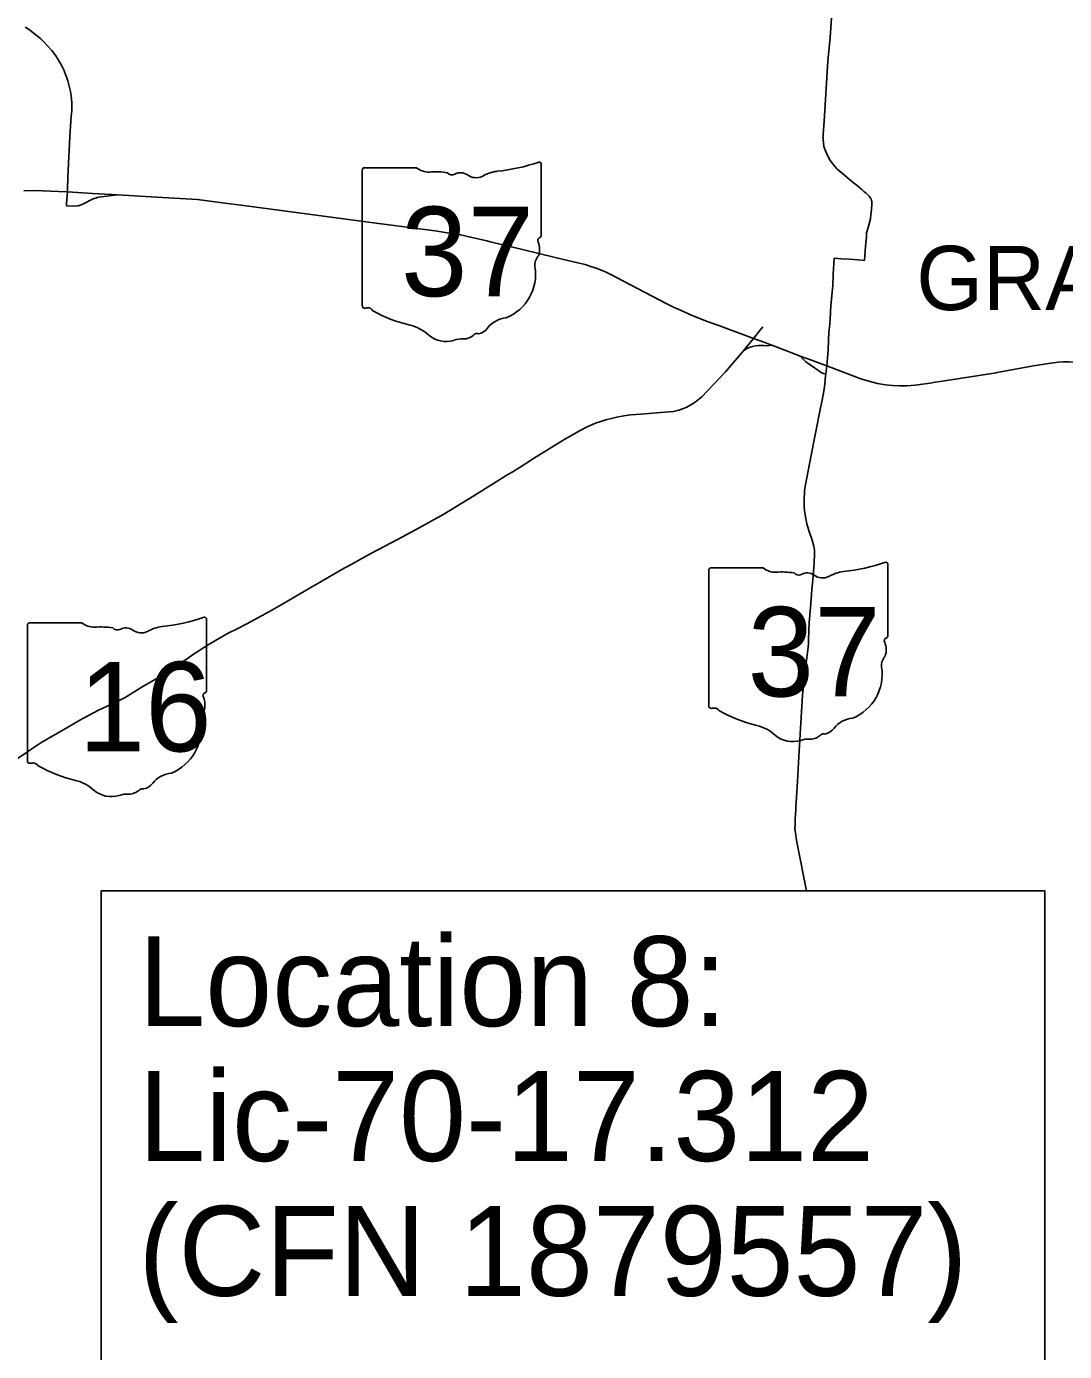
# Model space of a CAD drawing. Extents: x 1761803 to 2441803, y 509895 to 949895.
# Drawn here: x 1937717 to 1970029, y 814167 to 855435 of the extents above; entities that cross this region are included whole.
import ezdxf

# ---------------------------------------------------------------- set-up
doc = ezdxf.new("R2010")
doc.units = 0
for name, color, linetype in [('GM_X_County_Road', 7, 'Continuous'), ('GM_X_Minor_Lake', 7, 'Continuous'), ('GM_X_State_Location', 7, 'Continuous'), ('GM_X_Township_Road', 7, 'Continuous')]:
    doc.layers.add(name, color=color, linetype=linetype)

msp = doc.modelspace()

# ---------------------------------------------------------------- linework, layer by layer
at = {"layer": 'GM_X_Minor_Lake'}
for points in [[(1962543, 852489), (1962665, 854353), (1962733, 855092), (1962787, 855848)], [(1937683, 855414), (1937683, 855414), (1937817, 855317), (1938100, 855099), (1938165, 855046), (1938183, 855029)], [(1938183, 855029), (1938260, 854955), (1938375, 854837), (1938508, 854685), (1938596, 854567), (1938648, 854493), (1938673, 854454), (1938700, 854410), (1938728, 854365), (1938771, 854288), (1938800, 854240), (1938826, 854186), (1938876, 854081), (1938900, 854023), (1938932, 853945), (1938963, 853867), (1939008, 853738), (1939050, 853576), (1939082, 853415), (1939105, 853290), (1939118, 853160), (1939125, 853075), (1939132, 852947), (1939130, 852806), (1939110, 852644), (1939069, 852017), (1939041, 851551)], [(1962515, 852068), (1962543, 852489)], [(1962512, 851963), (1962511, 851970), (1962513, 852034), (1962515, 852068)], [(1962542, 851701), (1962515, 851919), (1962512, 851963)], [(1939041, 851551), (1939031, 851388), (1939007, 850734), (1939007, 850725)], [(1963645, 850419), (1963574, 850481), (1963408, 850612), (1963179, 850803), (1962945, 851006), (1962813, 851155), (1962736, 851261), (1962664, 851397), (1962589, 851562), (1962542, 851701)], [(1939007, 850725), (1938994, 850384)], [(1937633, 850319), (1937968, 850327), (1938957, 850286)], [(1938957, 850286), (1938991, 850284), (1939773, 850233), (1940356, 850205), (1940391, 850203), (1940551, 850193)], [(1938994, 850384), (1938991, 850284), (1938967, 849921), (1938963, 849849)], [(1938963, 849849), (1939223, 849842), (1939321, 849855), (1939417, 849885), (1939509, 849925), (1939684, 850016), (1939731, 850039), (1939776, 850059), (1939828, 850079), (1939871, 850092), (1939921, 850105), (1939968, 850116), (1940551, 850193)], [(1940551, 850193), (1941776, 850121), (1943039, 850045), (1943580, 849979), (1944712, 849830), (1947736, 849422), (1948517, 849321), (1949957, 849133), (1950437, 849072), (1950938, 848993), (1950961, 848989)], [(1963847, 850253), (1963797, 850291), (1963719, 850356), (1963645, 850419)], [(1963806, 848146), (1963833, 848598), (1963862, 848877), (1963864, 849004), (1963917, 849180), (1963985, 849450), (1964005, 849574), (1964023, 849723), (1964033, 849924), (1964034, 849948), (1964029, 849990), (1964020, 850021), (1964010, 850053), (1963997, 850079), (1963984, 850102), (1963968, 850124), (1963952, 850149), (1963927, 850175), (1963896, 850206), (1963847, 850253)], [(1950961, 848989), (1951231, 848948), (1951540, 848877), (1952048, 848755)], [(1952048, 848755), (1952152, 848729), (1952771, 848584), (1953669, 848367), (1954171, 848245), (1954920, 848067), (1955107, 848022), (1955288, 847964), (1955454, 847907), (1955737, 847795), (1955923, 847699), (1956280, 847517), (1957192, 847040), (1957604, 846816), (1957897, 846676)], [(1962776, 846947), (1962798, 847165), (1962813, 847364), (1962826, 847675), (1962829, 847725), (1962854, 848224)], [(1962854, 848224), (1963085, 848201), (1963331, 848185), (1963606, 848167), (1963806, 848146)], [(1962734, 846320), (1962758, 846758), (1962776, 846947)], [(1957897, 846676), (1957978, 846637), (1958443, 846437), (1958936, 846242), (1959270, 846118), (1959489, 846039), (1960049, 845832)], [(1960033, 845329), (1960160, 845494), (1960347, 845722), (1960548, 845970), (1960641, 846082)], [(1962629, 844865), (1962651, 845115), (1962668, 845347), (1962683, 845669), (1962697, 845903), (1962726, 846179), (1962734, 846320)], [(1960049, 845832), (1960292, 845742)], [(1960292, 845742), (1960340, 845724)], [(1960340, 845724), (1960347, 845722), (1960728, 845578), (1960771, 845562)], [(1957718, 843430), (1957860, 843446), (1958022, 843488), (1958173, 843541), (1958270, 843583), (1958469, 843698), (1958587, 843778), (1958742, 843906), (1959478, 844679), (1959962, 845246)], [(1959962, 845246), (1960033, 845329)], [(1960033, 845329), (1960144, 845406), (1960239, 845446)], [(1960239, 845446), (1960318, 845471), (1960407, 845488), (1960499, 845497), (1960666, 845495), (1960781, 845492), (1960914, 845507)], [(1960771, 845562), (1960914, 845507)], [(1960914, 845507), (1960998, 845476)], [(1960998, 845476), (1961831, 845162)], [(1961831, 845162), (1962187, 845029), (1962285, 844993)], [(1961831, 845162), (1961882, 845082), (1961981, 844993), (1962378, 844706), (1962460, 844652), (1962525, 844631), (1962602, 844620)], [(1962285, 844993), (1962629, 844865), (1963251, 844630)], [(1962602, 844620), (1962629, 844865)], [(1967922, 844654), (1969126, 844874), (1969608, 844952), (1969830, 844977), (1969983, 844986), (1970162, 844992), (1970318, 844982), (1970507, 844969), (1970771, 844931), (1971141, 844847), (1971333, 844790), (1971387, 844771), (1971438, 844753)], [(1962602, 844620), (1962584, 844465), (1962566, 844295), (1962533, 844080), (1962482, 843794), (1962436, 843555), (1962282, 842773)], [(1963251, 844630), (1963690, 844465), (1963936, 844387), (1964212, 844321), (1964462, 844278), (1964673, 844256), (1964894, 844242), (1965119, 844245), (1965396, 844265), (1965604, 844293), (1965920, 844342)], [(1965920, 844342), (1965935, 844344), (1966229, 844391), (1967899, 844649), (1967922, 844654)], [(1953008, 841665), (1953054, 841693), (1953500, 841978), (1954473, 842581), (1954732, 842731), (1954934, 842846), (1955149, 842956), (1955259, 843013), (1955432, 843080), (1955597, 843137), (1955753, 843182), (1955929, 843229), (1956097, 843267), (1956315, 843313), (1956515, 843343), (1956687, 843354), (1956837, 843366), (1957458, 843408), (1957714, 843429), (1957718, 843430)], [(1962282, 842773), (1962147, 842089), (1962051, 841593), (1961956, 841109), (1961937, 840982), (1961921, 840676), (1961923, 840574), (1961929, 840482), (1961939, 840347), (1961956, 840227), (1961976, 840109), (1962011, 839946), (1962074, 839733), (1962171, 839433), (1962226, 839247), (1962247, 839123), (1962248, 838999), (1962232, 838723), (1962190, 838206), (1962163, 837898), (1962129, 837458), (1962083, 836877), (1962064, 836339), (1962058, 836228), (1962049, 836100), (1961926, 835110), (1961876, 834614), (1961803, 833393), (1961749, 832517), (1961725, 832092), (1961697, 831595), (1961675, 831274), (1961669, 831120), (1961664, 831030), (1961661, 830975), (1961660, 830942), (1961646, 830721), (1961640, 830566), (1961639, 830433), (1961651, 830319), (1961672, 830160), (1961705, 829983), (1961994, 828511)], [(1936321, 831894), (1937775, 832868), (1937788, 832877), (1938194, 833146), (1938409, 833273), (1939024, 833621), (1939381, 833826), (1939960, 834141), (1940454, 834371), (1940785, 834540), (1941343, 834874), (1941809, 835150), (1942181, 835390), (1942441, 835560), (1942587, 835656), (1942719, 835744), (1942887, 835868), (1943377, 836176), (1943779, 836419), (1944020, 836552), (1944270, 836680), (1944552, 836817), (1944936, 837030), (1945286, 837214), (1945718, 837467), (1946245, 837773), (1947602, 838568), (1947726, 838631), (1948437, 839021), (1949285, 839468), (1949826, 839755), (1950703, 840249), (1951644, 840817), (1952702, 841479), (1952855, 841569), (1952918, 841608)], [(1952918, 841608), (1953008, 841665)]]:
    msp.add_lwpolyline(points, dxfattribs=at)
at = {"layer": 'GM_X_State_Location'}
msp.add_lwpolyline([(1940037, 813677), (1969413, 813677), (1969413, 828511), (1940037, 828511)], close=True, dxfattribs=at)
at = {"layer": 'GM_X_Township_Road'}
for p, q in [((1948171, 850964), (1948171, 846738)), ((1949857, 851037), (1948226, 851037)), ((1953740, 848931), (1953740, 851142)), ((1953739, 848931), (1953740, 848931)), ((1960646, 838572), (1959015, 838572)), ((1964529, 836466), (1964529, 838677)), ((1958960, 838500), (1958960, 834273)), ((1943320, 834755), (1943320, 836966)), ((1937752, 836788), (1937752, 832562)), ((1939437, 836861), (1937806, 836861)), ((1964528, 836467), (1964529, 836466)), ((1943320, 834755), (1943320, 834755))]:
    msp.add_line(p, q, dxfattribs=at)
for centre, radius, start, end in [((1948235, 850973), 64.5, 98.1301, 188.1301), ((1950245, 851528), 626, 231.6195, 271.1119), ((1951756, 856799), 5905, 275.8445, 288.9065), ((1953678, 851151), 62, 351.8621, 97.738), ((1950453, 848664), 2246, 80.4867, 94.9883), ((1950963, 850995), 181, 219.7921, 297.1024), ((1951228, 850507), 375, 54.4667, 119.1411), ((1951712, 851177), 452, 233.8562, 294.8282), ((1952510, 849746), 1188, 97.3462, 120.7689), ((1953674, 848922), 66.3, 289.6038, 7.7341), ((1953726, 848768), 95.9, 107.944, 210.337), ((1953115, 848489), 576, 340.033, 23.6496), ((1953962, 848006), 419, 136.8065, 186.9296), ((1952087, 847724), 1477, 292.3089, 8.9858), ((1948236, 846728), 65.1, 171.9584, 258.3066), ((1948246, 847161), 497, 267.339, 280.6039), ((1948347, 846494), 179, 29.7484, 93.2717), ((1950608, 850291), 4265, 240.4129, 257.1985), ((1949337, 844839), 1334, 47.1842, 75.836), ((1951685, 846328), 477, 282.8732, 323.2771), ((1952710, 845551), 809, 94.4031, 142.5768), ((1950780, 846473), 847, 230.7004, 286.2918), ((1951269, 845012), 696, 85.6951, 111.2099), ((1951331, 846156), 451, 268.777, 315.5493), ((1951739, 845747), 127, 65.7517, 132.6484), ((1959024, 838509), 64.5, 98.1301, 188.1301), ((1961034, 839063), 626, 231.6195, 271.1119), ((1962545, 844335), 5905, 275.8445, 288.9065), ((1964467, 838686), 62, 351.8621, 97.738), ((1961242, 836200), 2246, 80.4867, 94.9883), ((1961752, 838531), 181, 219.7921, 297.1024), ((1962017, 838042), 375, 54.4667, 119.1411), ((1962501, 838712), 452, 233.8562, 294.8282), ((1963299, 837281), 1188, 97.3462, 120.7689), ((1941337, 842623), 5905, 275.8445, 288.9065), ((1943258, 836975), 62, 351.8621, 97.738), ((1937815, 836797), 64.5, 98.1301, 188.1301), ((1939826, 837351), 626, 231.6195, 271.1119), ((1940033, 834488), 2246, 80.4867, 94.9883), ((1940543, 836819), 181, 219.7921, 297.1024), ((1940808, 836330), 375, 54.4667, 119.1411), ((1941292, 837000), 452, 233.8562, 294.8282), ((1942090, 835570), 1188, 97.3462, 120.7689), ((1964515, 836304), 95.9, 107.944, 210.337), ((1963904, 836024), 576, 340.033, 23.6496), ((1964463, 836458), 66.3, 289.6038, 7.7341), ((1964751, 835541), 419, 136.8065, 186.9296), ((1962876, 835260), 1477, 292.3089, 8.9858), ((1943306, 834592), 95.9, 107.944, 210.337), ((1942696, 834313), 576, 340.033, 23.6496), ((1943254, 834746), 66.3, 289.6038, 7.7341), ((1943542, 833829), 419, 136.8065, 186.9296), ((1959025, 834264), 65.1, 171.9584, 258.3066), ((1959035, 834696), 497, 267.339, 280.6039), ((1959136, 834029), 179, 29.7484, 93.2717), ((1961397, 837827), 4265, 240.4129, 257.1985), ((1941667, 833548), 1477, 292.3089, 8.9858), ((1960126, 832374), 1334, 47.1842, 75.836), ((1963499, 833086), 809, 94.4031, 142.5768), ((1961569, 834008), 847, 230.7004, 286.2918), ((1962058, 832547), 696, 85.6951, 111.2099), ((1962120, 833692), 451, 268.777, 315.5493), ((1962528, 833282), 127, 65.7517, 132.6484), ((1962474, 833863), 477, 282.8732, 323.2771), ((1937816, 832552), 65.1, 171.9584, 258.3066), ((1937826, 832985), 497, 267.339, 280.6039), ((1937927, 832318), 179, 29.7484, 93.2717), ((1940189, 836115), 4265, 240.4129, 257.1985), ((1942290, 831375), 809, 94.4031, 142.5768), ((1938917, 830663), 1334, 47.1842, 75.836), ((1940360, 832297), 847, 230.7004, 286.2918), ((1940911, 831980), 451, 268.777, 315.5493), ((1941319, 831571), 127, 65.7517, 132.6484), ((1941265, 832152), 477, 282.8732, 323.2771), ((1940849, 830835), 696, 85.6951, 111.2099)]:
    msp.add_arc(centre, radius, start, end, dxfattribs=at)

# ---------------------------------------------------------------- texts
at = {"layer": 'GM_X_County_Road'}
msp.add_text('GRANVILLE', height=2000, rotation=0, dxfattribs=at).set_placement((1965415, 846603))
at = {"layer": 'GM_X_State_Location'}
for s, p in [('Location 8:', (1941200, 824301)), ('Lic-70-17.312', (1941200, 820101)), ('(CFN 1879557)', (1941200, 815901))]:
    msp.add_text(s, height=2800, dxfattribs=at).set_placement(p)
at = {"layer": 'GM_X_Township_Road'}
for s, p in [('37', (1949373, 847036)), ('37', (1960162, 834571)), ('16', (1939339, 832860))]:
    msp.add_text(s, height=2784.4, dxfattribs=at).set_placement(p)

doc.saveas('drawing.dxf')
